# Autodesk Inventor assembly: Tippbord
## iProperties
Author: Tobben
Created: 2001-12
Part Number: Tippbord
Document SubType Name: Assembly
Designer: Tobben
Control State: 0
Master: False
Checked Out: False
PropertySet Name: Design Tracking Control
Shininess: 64.0
Angle Display Precision: 2
Document Length Units: 11269
Document Angle Units: 11283
Document Time Units: 11279
Document Mass Units: 11290
Document Length Units Precision: 3
Document Angle Units Precision: 2
Compacted: False
PropertySet Name: _Private Model Information
Density: 0.0
Volumn: 0.0
Area: 0.0
PropertySet Name: Model Information
